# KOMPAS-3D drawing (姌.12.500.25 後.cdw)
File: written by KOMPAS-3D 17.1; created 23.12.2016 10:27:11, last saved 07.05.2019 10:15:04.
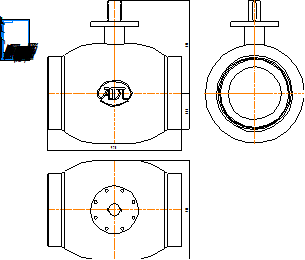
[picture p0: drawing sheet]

Sheet 1: A4, portrait

Title block, sheet 1: name: КШ.12.500.25 сс; material: Внимание! Данный продукт является объектом авторского права ООО «Торговый Дом АДЛ». / Запрещается изменение, копирование, распространение / (в том числе путем копирования на другие сайты и ресурсы в Интернете) / или любое иное использование информации и объектов без предварительного / согласия правообладателя (ООО «Торговый Дом АДЛ»).; sheets: 1; organisation: ООО "Торговый дом АДЛ"; sheet format: A4; stored path: C:\Users\tra\Desktop\2д чертежи\Шаровые краны БИВАЛ\КШ_Бивал_серия_11_12\KOMPAS_2D\КШ.12.500.25 сс.cdw

Views: Вид 1, Проекционный вид 2, Проекционный вид 3
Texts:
  Klimkovich
  ADL
Dimensions and other numbers on the sheet: 970; 673; 265; 720; 1:1; 1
